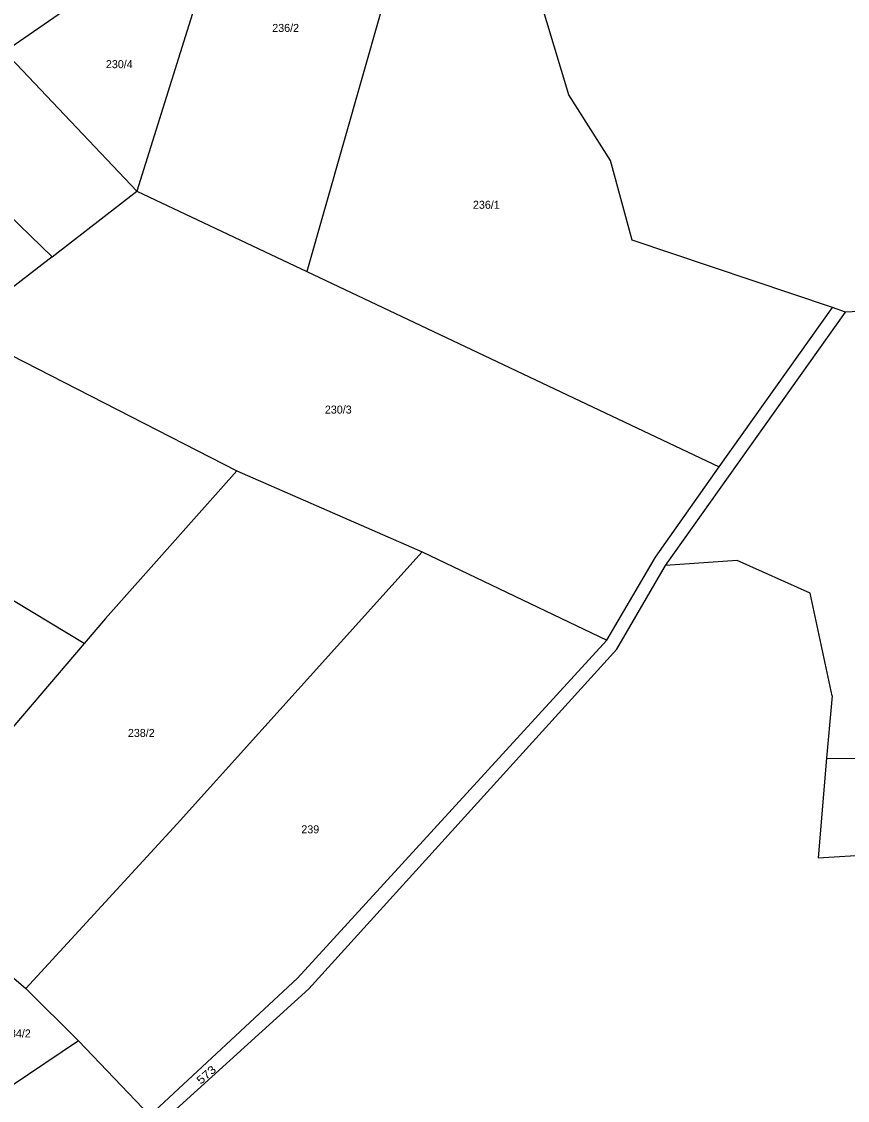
# Model space of a CAD drawing. Extents: x -664548 to -662415, y -1069720 to -1068208.
# Drawn here: x -662907.1 to -662731.7, y -1068674.7 to -1068445.5 of the extents above; entities that cross this region are included whole.
import ezdxf

# ---------------------------------------------------------------- set-up
doc = ezdxf.new("R2010")
doc.units = 0
doc.header["$LTSCALE"] = 0.68
doc.layers.add('1', color=7, linetype='Continuous', lineweight=25)
doc.layers.add('2', color=7, linetype='Continuous')

msp = doc.modelspace()

# ---------------------------------------------------------------- linework, layer by layer
at = {"layer": '1'}
for p, q in [((-662910.77, -1068451.83), (-662863.05, -1068418.84)), ((-662863.05, -1068418.84), (-662882.62, -1068481.52)), ((-662790.85, -1068461.07), (-662799.53, -1068432.21)), ((-662882.62, -1068481.52), (-662910.77, -1068451.83)), ((-662782.02, -1068475.03), (-662790.85, -1068461.07)), ((-662900.61, -1068495.45), (-662931.21, -1068465.97)), ((-662777.41, -1068491.96), (-662782.02, -1068475.03)), ((-662900.61, -1068495.45), (-662882.62, -1068481.52)), ((-662882.62, -1068481.52), (-662846.55, -1068498.6)), ((-662734.9, -1068506.25), (-662777.41, -1068491.96)), ((-662900.61, -1068495.45), (-662920.38, -1068510.76)), ((-662638.49, -1068502.62), (-662732.11, -1068507.19)), ((-662732.11, -1068507.19), (-662734.9, -1068506.25)), ((-662770.33, -1068561.07), (-662732.11, -1068507.19)), ((-662920.38, -1068510.76), (-662861.37, -1068540.96)), ((-662861.37, -1068540.96), (-662889.29, -1068572.31)), ((-662861.37, -1068540.96), (-662822.03, -1068558.12)), ((-662772.51, -1068559.27), (-662758.92, -1068540.11)), ((-662893.84, -1068577.64), (-662940.67, -1068549.42)), ((-662874.08, -1068615.98), (-662822.03, -1068558.12)), ((-662822.03, -1068558.12), (-662782.83, -1068576.91)), ((-662782.83, -1068576.91), (-662772.51, -1068559.27)), ((-662780.72, -1068578.82), (-662770.33, -1068561.07)), ((-662755.16, -1068559.97), (-662770.33, -1068561.07)), ((-662739.59, -1068566.91), (-662755.16, -1068559.97)), ((-662734.98, -1068588.78), (-662739.59, -1068566.91)), ((-662889.29, -1068572.31), (-662893.84, -1068577.64)), ((-662893.84, -1068577.64), (-662935.06, -1068625.96)), ((-662782.83, -1068576.91), (-662848.55, -1068648.75)), ((-662780.72, -1068578.82), (-662846.14, -1068650.99)), ((-662734.98, -1068588.78), (-662736.12, -1068602.02)), ((-662736.12, -1068602.02), (-662737.94, -1068623.17)), ((-662736.12, -1068602.02), (-662647.51, -1068602.52)), ((-662906.21, -1068650.93), (-662874.08, -1068615.98)), ((-662737.94, -1068623.17), (-662649.98, -1068617.75)), ((-662910.8, -1068646.96), (-662906.21, -1068650.93)), ((-662848.55, -1068648.75), (-662879.87, -1068677.92)), ((-662906.21, -1068650.93), (-662895.01, -1068662.05)), ((-662895.01, -1068662.05), (-662909.12, -1068671.53)), ((-662895.01, -1068662.05), (-662879.87, -1068677.92))]:
    msp.add_line(p, q, dxfattribs=at)
for points in [[(-662850.03, -1068391.18), (-662819.1, -1068402.3), (-662846.55, -1068498.6)], [(-662846.55, -1068498.6), (-662758.92, -1068540.11), (-662734.9, -1068506.25)], [(-662846.14, -1068650.99), (-662876.64, -1068678.68), (-662825.07, -1068766.52)]]:
    msp.add_lwpolyline(points, dxfattribs=at)

# ---------------------------------------------------------------- texts
at = {"layer": '2'}
for s, p in [('236/2', (-662853.88, -1068447.675)), ('230/4', (-662889.21, -1068455.375)), ('236/1', (-662811.25, -1068485.255)), ('230/3', (-662842.7, -1068528.775)), ('238/2', (-662884.54, -1068597.485)), ('239', (-662847.7, -1068617.965)), ('184/2', (-662910.86, -1068661.344))]:
    msp.add_text(s, height=1.7, dxfattribs=at).set_placement(p)
at = {"layer": '2', "width": 1.2}
msp.add_text('573', height=1.7, rotation=41, dxfattribs=at).set_placement((-662869.061, -1068671.41))

doc.saveas('drawing.dxf')
